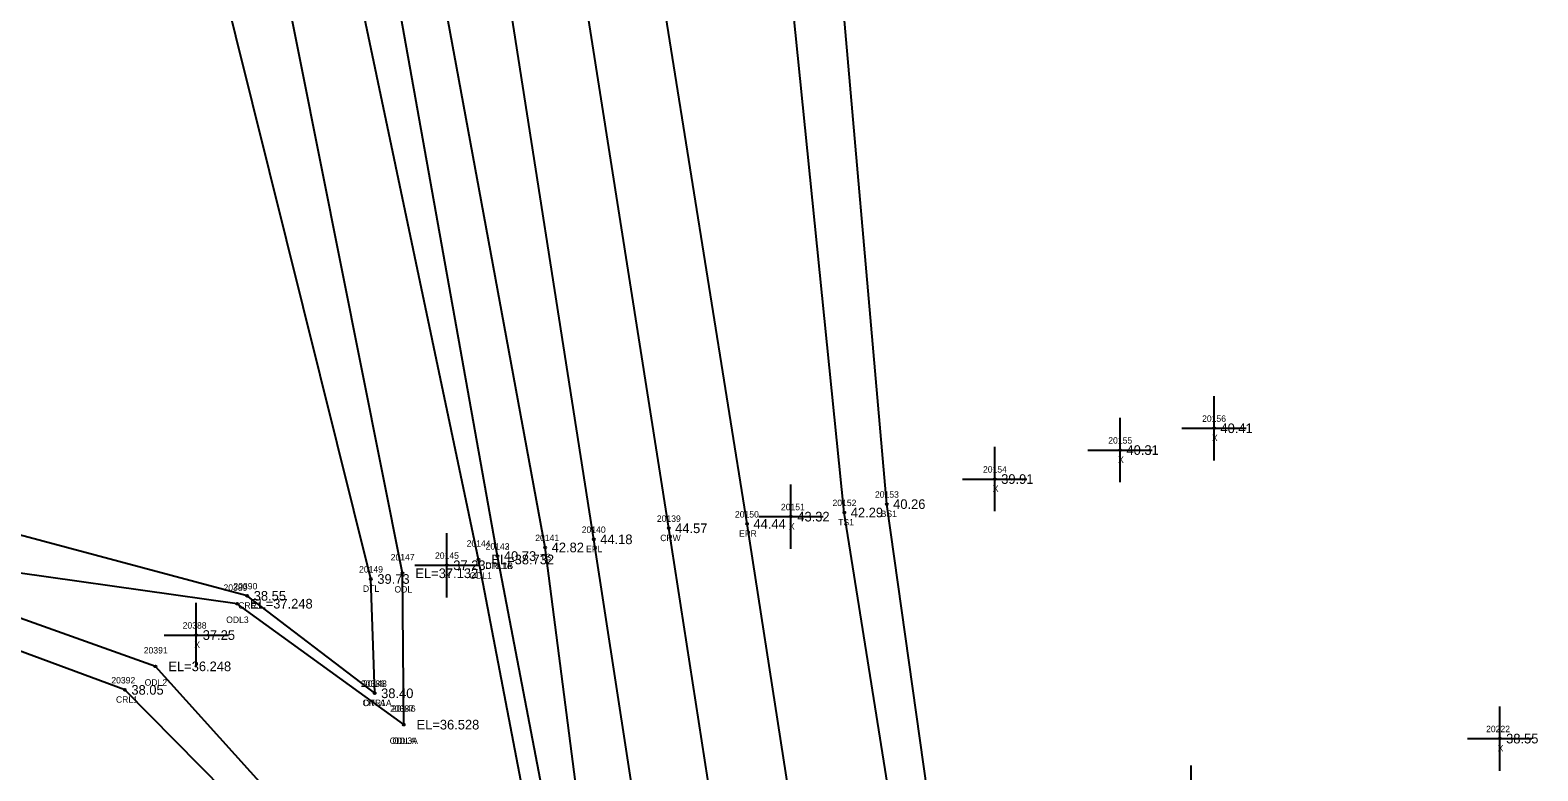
# Model space of a CAD drawing. Extents: x 2619569 to 2620117, y 784503 to 785150.
# Drawn here: x 2619719.1 to 2619953.5, y 784899.6 to 785014.8 of the extents above; entities that cross this region are included whole.
import ezdxf

# ---------------------------------------------------------------- set-up
doc = ezdxf.new("R2010")
doc.units = 0
for name, color, linetype in [('RD_DTM_BkLn1', 7, 'Continuous'), ('RD_DTM_BkLn2', 7, 'Continuous'), ('RD_DTM_BkLn_txCode', 7, 'Continuous'), ('RD_EX_H2O', 7, 'Continuous'), ('RD_EX_H2O_txCode', 7, 'Continuous'), ('RD_EX_Misc', 7, 'Continuous'), ('RD_EX_Misc_txCode', 7, 'Continuous'), ('RD_EX_Road', 7, 'Continuous'), ('RD_EX_Road_txCode', 7, 'Continuous'), ('RD_EX_TX_H2O_ELEV', 7, 'Continuous'), ('RD_EX_TX_Misc_ELEV', 7, 'Continuous'), ('RD_EX_TX_Road_ELEV', 7, 'Continuous'), ('RD_HC_Survey_ELEV', 7, 'Continuous'), ('RD_HC_Survey_txCode', 7, 'Continuous'), ('RD_SMD_Locator', 7, 'Continuous')]:
    doc.layers.add(name, color=color, linetype=linetype)

msp = doc.modelspace()

# ---------------------------------------------------------------- linework, layer by layer
at = {"layer": 'RD_DTM_BkLn1'}
msp.add_lwpolyline([(2619832.4, 784847.12), (2619818.36, 784937.35), (2619803.19, 785033.82), (2619788.17, 785128.62)], dxfattribs=at)
at = {"layer": 'RD_DTM_BkLn2'}
for points in [[(2619858.56, 784858.85), (2619845.67, 784939.8), (2619836.14, 785033.44), (2619815.08, 785132.91)], [(2619863.71, 784859.84), (2619852.26, 784941.11), (2619844.14, 785034.21), (2619822.19, 785133.61)], [(2619819.74, 784845.33), (2619814.01, 784845.92), (2619808.4, 784862.96), (2619799.16, 784934.37), (2619781.54, 785030.11), (2619769.89, 785089.15), (2619763.91, 785131.01)]]:
    msp.add_lwpolyline(points, dxfattribs=at)
at = {"layer": 'RD_EX_H2O'}
for points in [[(2619772.64, 784911.68), (2619772.05, 784929.46), (2619748.39, 785024.59), (2619738.12, 785085.25), (2619757.14, 785100.38)], [(2619791.73, 784933.03), (2619763.93, 785088.41), (2619762.47, 785100.82), (2619757.14, 785100.38)], [(2619777.15, 784906.8), (2619776.97, 784930.35), (2619757.87, 785026.13), (2619750.03, 785086.71), (2619758.97, 785087.81)], [(2619818.98, 784834.06), (2619808.97, 784842.56), (2619802.24, 784862.11), (2619788.78, 784932.49), (2619768.72, 785027.95), (2619758.97, 785087.81)], [(2619772.64, 784911.68), (2619752.83, 784926.84), (2619712.83, 784937.52), (2619673.24, 784936.72), (2619647.77, 784928.32), (2619603.54, 784903.62)], [(2619819.63, 784843.41), (2619811.5, 784844.43), (2619805.32, 784862.13), (2619791.73, 784933.03)], [(2619777.15, 784906.8), (2619751.24, 784925.62), (2619707.2, 784931.84), (2619672.79, 784931.74), (2619648.09, 784923.33), (2619611.01, 784900.54)], [(2619790.27, 784838.72), (2619782.87, 784866.71), (2619738.56, 784915.87), (2619703.69, 784928.29), (2619672.34, 784926.76), (2619648.41, 784918.34), (2619619.29, 784887.62)], [(2619773.83, 784850.15), (2619780.57, 784864.79), (2619733.81, 784912.21), (2619700.27, 784924.63), (2619672.07, 784923.77), (2619649.36, 784903.37), (2619624.57, 784890.48)]]:
    msp.add_lwpolyline(points, dxfattribs=at)
at = {"layer": 'RD_EX_Misc'}
for p, q in [((2619903.16, 784947.91), (2619903.16, 784957.91)), ((2619888.54, 784944.52), (2619888.54, 784954.52)), ((2619898.16, 784952.91), (2619908.16, 784952.91)), ((2619869.06, 784940.01), (2619869.06, 784950.01)), ((2619883.54, 784949.52), (2619893.54, 784949.52)), ((2619864.06, 784945.01), (2619874.06, 784945.01)), ((2619837.36, 784934.16), (2619837.36, 784944.16)), ((2619832.36, 784939.16), (2619842.36, 784939.16)), ((2619783.86, 784926.6), (2619783.86, 784936.6)), ((2619778.86, 784931.6), (2619788.86, 784931.6)), ((2619744.9, 784915.74), (2619744.9, 784925.74)), ((2619739.9, 784920.74), (2619749.9, 784920.74)), ((2619947.58, 784899.63), (2619947.58, 784909.63)), ((2619942.58, 784904.63), (2619952.58, 784904.63)), ((2619899.59, 784890.44), (2619899.59, 784900.44))]:
    msp.add_line(p, q, dxfattribs=at)
at = {"layer": 'RD_EX_Road'}
for points in [[(2619820.6, 784845.48), (2619829.43, 784847.3), (2619832.4, 784847.12), (2619843.47, 784848.15), (2619843.67, 784853.02), (2619841.88, 784865.21), (2619830.54, 784938.02), (2619815.78, 785030.4), (2619811.4, 785059.13), (2619800.29, 785130.22)], [(2619820.6, 784845.48), (2619806.71, 784935.63), (2619791.64, 785032.01), (2619776.96, 785126.6)]]:
    msp.add_lwpolyline(points, dxfattribs=at)
at = {"layer": 'RD_SMD_Locator'}
for centre in [(2619903.16, 784952.91), (2619888.54, 784949.52), (2619869.06, 784945.01), (2619845.67, 784939.8), (2619852.26, 784941.11), (2619818.36, 784937.35), (2619830.54, 784938.02), (2619837.36, 784939.16), (2619806.71, 784935.63), (2619791.73, 784933.03), (2619791.73, 784933.03), (2619799.16, 784934.37), (2619776.97, 784930.35), (2619783.86, 784931.6), (2619788.78, 784932.49), (2619772.05, 784929.46), (2619752.83, 784926.84), (2619751.24, 784925.62), (2619744.9, 784920.74), (2619738.56, 784915.87), (2619733.81, 784912.21), (2619772.64, 784911.68), (2619772.64, 784911.68), (2619777.15, 784906.8), (2619777.15, 784906.8), (2619947.58, 784904.63)]:
    msp.add_circle(centre, 0.15, dxfattribs=at)

# ---------------------------------------------------------------- texts
at = {"layer": 'RD_DTM_BkLn_txCode'}
for s, p in [('20153', (2619850.43, 784942.11)), ('20152', (2619843.83, 784940.8)), ('BS1', (2619851.32, 784939.11)), ('TS1', (2619844.71, 784937.8)), ('20141', (2619797.61, 784935.37)), ('TS', (2619798.37, 784932.37))]:
    msp.add_text(s, height=1, dxfattribs=at).set_placement(p)
at = {"layer": 'RD_EX_H2O_txCode'}
for s, p in [('20144', (2619786.94, 784934.49)), ('20147', (2619775.13, 784932.35)), ('20142', (2619789.89, 784934.03)), ('20143', (2619789.89, 784934.03)), ('20149', (2619770.21, 784930.46)), ('ODL1', (2619787.37, 784929.49)), ('CRL1B', (2619789.86, 784931.03)), ('DTL1A', (2619789.83, 784931.03)), ('20389', (2619749.13, 784927.62)), ('20390', (2619750.67, 784927.84)), ('DTL', (2619770.81, 784927.46)), ('ODL', (2619775.72, 784927.35)), ('CRR1', (2619751.41, 784924.84)), ('ODL3', (2619749.55, 784922.62)), ('20391', (2619736.73, 784917.87)), ('20392', (2619731.69, 784913.21)), ('ODL2', (2619736.87, 784912.87)), ('20386', (2619770.5, 784912.68)), ('20148', (2619770.81, 784912.68)), ('CRL1', (2619732.41, 784910.21)), ('CRR1A', (2619770.74, 784909.68)), ('DTLA', (2619770.91, 784909.68)), ('20387', (2619775.03, 784908.8)), ('20146', (2619775.29, 784908.8)), ('ODL3A', (2619774.97, 784903.8)), ('ODLA', (2619775.42, 784903.8))]:
    msp.add_text(s, height=1, dxfattribs=at).set_placement(p)
at = {"layer": 'RD_EX_Misc_txCode'}
for s, p in [('20156', (2619901.3, 784953.91)), ('X', (2619902.84, 784950.91)), ('20155', (2619886.71, 784950.52)), ('20154', (2619867.23, 784946.01)), ('X', (2619888.23, 784947.52)), ('X', (2619868.75, 784943.01)), ('20151', (2619835.81, 784940.16)), ('X', (2619837.05, 784937.16)), ('20145', (2619782.02, 784932.6)), ('X', (2619783.54, 784929.6)), ('20388', (2619742.78, 784921.74)), ('X', (2619744.59, 784918.74)), ('20222', (2619945.46, 784905.63)), ('X', (2619947.26, 784902.63))]:
    msp.add_text(s, height=1, dxfattribs=at).set_placement(p)
at = {"layer": 'RD_EX_Road_txCode'}
for s, p in [('20150', (2619828.66, 784939.02)), ('20140', (2619804.84, 784936.63)), ('EPR', (2619829.31, 784936.02)), ('EPL', (2619805.51, 784933.63))]:
    msp.add_text(s, height=1, dxfattribs=at).set_placement(p)
at = {"layer": 'RD_EX_TX_H2O_ELEV'}
for s, p in [('EL=38.732', (2619790.78, 784931.74)), ('40.73', (2619792.73, 784932.28)), ('40.73', (2619792.73, 784932.28)), ('EL=37.132', (2619778.97, 784929.6)), ('39.73', (2619773.05, 784928.71)), ('EL=37.248', (2619753.24, 784924.87)), ('38.55', (2619753.83, 784926.09)), ('EL=36.248', (2619740.56, 784915.12)), ('38.05', (2619734.81, 784911.46)), ('38.40', (2619773.64, 784910.93)), ('38.40', (2619773.64, 784910.93)), ('EL=36.528', (2619779.15, 784906.05)), ('EL=36.528', (2619779.15, 784906.05))]:
    msp.add_text(s, height=1.5, dxfattribs=at).set_placement(p)
at = {"layer": 'RD_EX_TX_Misc_ELEV'}
for s, p in [('40.41', (2619904.16, 784952.16)), ('40.31', (2619889.54, 784948.77)), ('39.91', (2619870.06, 784944.26)), ('43.32', (2619838.36, 784938.41)), ('42.29', (2619846.67, 784939.05)), ('40.26', (2619853.26, 784940.36)), ('42.82', (2619800.16, 784933.62)), ('37.23', (2619784.86, 784930.85)), ('37.25', (2619745.9, 784919.99)), ('38.55', (2619948.58, 784903.88))]:
    msp.add_text(s, height=1.5, dxfattribs=at).set_placement(p)
at = {"layer": 'RD_EX_TX_Road_ELEV'}
for s, p in [('44.44', (2619831.54, 784937.27)), ('44.18', (2619807.71, 784934.88))]:
    msp.add_text(s, height=1.5, dxfattribs=at).set_placement(p)
at = {"layer": 'RD_HC_Survey_ELEV'}
msp.add_text('44.57', height=1.5, dxfattribs=at).set_placement((2619819.36, 784936.6))
at = {"layer": 'RD_HC_Survey_txCode'}
for s, p in [('20139', (2619816.52, 784938.35)), ('CRW', (2619817.04, 784935.35))]:
    msp.add_text(s, height=1, dxfattribs=at).set_placement(p)

doc.saveas('drawing.dxf')
